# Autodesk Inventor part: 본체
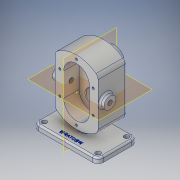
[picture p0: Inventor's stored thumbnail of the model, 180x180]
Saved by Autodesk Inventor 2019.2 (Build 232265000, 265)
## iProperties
Created: 2019-03
Part Number: 본체
Material: 알루미늄 6061
Document SubType Name: Modeling
Designer: User
Density: 2.7 g/cm^3
Appearance: 알루미늄 - 평지
Mass: 1189.14 g
Surface Area: 719.935 cm^2
Volume: 440.421 cm^3
Author: User
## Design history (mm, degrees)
sketch "스케치4"
  geometry: L1 (0, 87.6)-(0, -105.6) reference; L2 (-84, 0)-(84, 0) reference; L3 (40, 44.721)-(40, -44.721); L4 (-40, 44.721)-(-40, -44.721); A1 r 60 centre (0, 0) between (-40, -44.721) and (40, -44.721); A2 r 60 centre (0, 0) between (40, 44.721) and (-40, 44.721); 2 further points
  constraints: 4 end point, 4 point on circle, 2 centre point, 1 symmetric about line, 1 vertical
  dimensions: "d30" = 0 distance from line of L1 A1.centre; "d31" = 0 distance from line of L2 A1.centre; "d33" = 40 distance between parallel lines of L1 L4; "d34" = 80 distance between parallel lines of L3 L4; "d35" = 60 radius of A2; "d36" = 60 radius of A1
extrude "돌출1" new body sketch "스케치4" distance "d22" = 53; taper "d23" = 0 deg
sketch "스케치5"
  geometry: L1 (-60, -68)-(60, -68); L2 (60, -68)-(60, -78); L3 (60, -78)-(-60, -78); L4 (-60, -78)-(-60, -68); L5 (0, 87.6)-(0, -105.6) reference; L6 (-84, 0)-(84, 0) reference; 1 further point
  constraints: 8 end point, 2 parallel, 1 horizontal, 1 perpendicular
  dimensions: "d24" = 10 distance of L1.end L2.end; "d25" = 120 distance of L2.end L3.end; "d26" = 60 distance between parallel lines of L5 L2; "d27" = 78 distance between parallel lines of L6 L3
extrude "돌출2" join sketch "스케치5" distance "d37" = 20; taper "d39" = 0 deg; dims "d38" = 53, "d40" = 0
sketch "스케치6"
  geometry: L1 (0, -105.6)-(0, 87.6) reference; L2 (-84, 0)-(84, 0) reference; C1 r 19.396 at (0, 22); 1 further point
  constraints: 1 centre point
  dimensions: "d41" = 0 distance from line of L1 C1.centre; "d42" = 22 distance from line of L2 C1.centre
extrude "돌출3" join sketch "스케치6" distance "d43" = 17; taper "d44" = 0 deg
sketch "스케치7"
  geometry: L1 (-38, 44.721)-(88, 44.721) reference; L2 (-20, -33.279)-(-20, -23.279) reference; L3 (0, 0)-(0, 89.443) reference; C1 r 11 at (14, 44.721); 1 further point
  constraints: 1 centre point
  dimensions: "d45" = 0 distance from line of L1 C1.centre; "d46" = 22 diameter of C1; "d124" = 14 distance from line of C1.centre L3
extrude "돌출4" join sketch "스케치7" distance "d48" = 8; taper "d49" = 0 deg
sketch "스케치8"
  geometry: L1 (-68, -53)-(-68, 20) reference; L2 (-68, -10)-(-55.776, -10); L3 (-55.776, -10)-(-55.776, -53); L4 (-55.776, -53)-(-68, -53); L5 (-68, -53)-(-68, -10); L6 (-105.6, 0)-(87.6, 0) reference; 1 further point
  constraints: 8 end point, 2 parallel, 1 horizontal, 1 perpendicular, 1 point on line
  dimensions: "d50" = 43 distance of L2.end L3.end; "d51" = 12.2244 distance of L3.end L4.end; "d52" = 10 distance between parallel lines of L6 L2
extrude "돌출5" join sketch "스케치8" stored distance "d53" = 12; taper "d54" = 0 deg
sketch "스케치9"
  geometry: L1 (0, 87.6)-(0, -105.6) reference; L2 (-84, 0)-(84, 0) reference; L3 (24, 22)-(24, -22); L4 (-24, 22)-(-24, -22); A1 r 24 centre (0, 22) between (24, 22) and (-24, 22); A2 r 24 centre (0, -22) between (-24, -22) and (24, -22); 1 further point
  constraints: 4 end point, 4 point on circle, 2 centre point, 2 tangent, 2 vertical
  dimensions: "d55" = 48 diameter of A1; "d56" = 48 diameter of A2; "d57" = 0 distance from line of L1 A1.centre; "d58" = 0 distance from line of L1 A2.centre; "d59" = 22 distance from line of L2 A1.centre; "d60" = 44 distance of A1.centre A2.centre
extrude "돌출6" cut sketch "스케치9" distance "d61" = 29; taper "d62" = 0 deg
sketch "스케치10"
  geometry: L1 (0, 87.6)-(0, -105.6) reference; L2 (-84, 0)-(84, 0) reference; C1 r 12.5 at (0, 22); C2 r 12.5 at (0, -22); 1 further point
  constraints: 2 centre point
  dimensions: "d63" = 25 diameter of C2; "d64" = 25 diameter of C1; "d65" = 0 distance from line of L1 C1.centre; "d66" = 0 distance from line of L1 C2.centre; "d67" = 44 distance of C1.centre C2.centre; "d68" = 22 distance from line of L2 C1.centre
extrude "돌출7" cut sketch "스케치10" distance "d69" = 15; taper "d70" = 0 deg
sketch "스케치11"
  geometry: C1 r 19.396 at (0, 0) reference; 2 further points
  constraints: 1 coincident
hole "구멍1" sketch "스케치11" at (0, 0) diameter "d71" = 17; stored, may be unused: countersink angle "d75" = 90 deg, drill point angle "d77" = 0 deg; dims "d72" = 8, "d73" = 28, "d74" = 7.3, "d76" = 30
sketch "스케치12"
  geometry: C1 r 11 at (0, 0) reference; 2 further points
  constraints: 1 coincident
hole "구멍2" sketch "스케치12" at (0, 0) diameter "d78" = 8.376; stored, may be unused: countersink angle "d82" = 90 deg, drill point angle "d84" = 118 deg; dims "d79" = 200, "d80" = 28, "d81" = 7.3, "d83" = 27.3
fillet "모깎기1" dims "d85" = 10
sketch "스케치13"
  geometry: L1 (-84, 0)-(84, 0) reference; C1 r 12.5 at (0, 22) reference; A1 r 31 centre (0, 22) between (-31, 22) and (31, 22); 2 further points
  constraints: 2 point on circle, 1 centre point, 1 coincident
  dimensions: "d93" = 62 diameter of A1; "d94" = 0 horizontal distance of A1.centre point (0, 53); "d95" = 31 distance of A1.centre point (0, 53); "d96" = 22 distance from line of L1 A1.end; "d97" = 22 distance from line of L1 A1.start
hole "구멍3" sketch "스케치13" at (0, 53), (31, 22), (-31, 22) diameter "d86" = 4.134; stored, may be unused: countersink angle "d90" = 90 deg, drill point angle "d92" = 118 deg; dims "d87" = 10, "d88" = 28, "d89" = 7.3, "d91" = 12
sketch "스케치15"
  geometry: A1 r 10 centre (-44, -20) between (-54, -20) and (-44, -30) reference; A2 r 10 centre (56, -20) between (56, -30) and (66, -20) reference; A3 r 10 centre (56, 33) between (66, 33) and (56, 43) reference; A4 r 10 centre (-44, 33) between (-44, 43) and (-54, 33) reference; 5 further points
  constraints: 4 coincident
hole "구멍4" sketch "스케치15" at (-44, -20), (56, -20), (56, 33), (-44, 33) diameter "d98" = 9; stored, may be unused: countersink angle "d102" = 90 deg, drill point angle "d104" = 118 deg; dims "d99" = 10, "d100" = 28, "d101" = 7.3, "d103" = 12
fillet "모깎기2" dims "d105" = 3
fillet "모깎기3" dims "d106" = 3
fillet "모깎기4" dims "d107" = 10
fillet "모깎기5" dims "d108" = 3
fillet "모깎기6" dims "d109" = 3
fillet "모깎기7" dims "d110" = 3
fillet "모깎기8" dims "d111" = 3
fillet "모깎기9" dims "d112" = 2
chamfer "모따기1" distance "d113" = 1; stored, may be unused: second distance "d114" = 2, angle "d115" = 45 deg
fillet "모깎기10" dims "d116" = 0.5
chamfer "모따기2" distance "d117" = 0.7; stored, may be unused: second distance "d118" = 2, angle "d119" = 30 deg
sketch "스케치16"
  geometry: 1 further point
sketch "스케치17" dims "d64" = 25
  geometry: L1 (-57, 36)-(-57, -17) reference; L2 (-47, -27)-(53, -27) reference; 2 further points
  constraints: 1 other
  dimensions: "d120" = 60 distance from line of L1 point (3, -17); "d121" = 10 distance from line of L2 point (3, -17)
feature "엠보싱1" sketch "스케치17" dims "d122" = 0.5, "d123" = 0
node "솔리드1"
mirror "미러1"
mirror "미러2"
